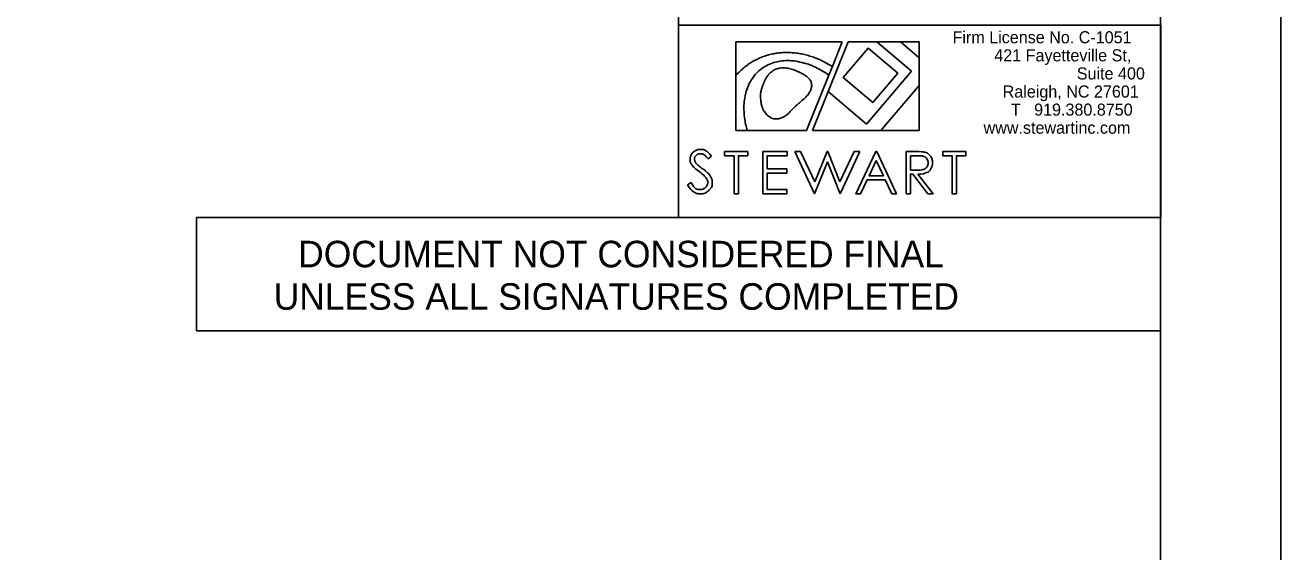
# Model space of a CAD drawing. Extents: x 972 to 1006, y 10585.8 to 10607.8.
# Drawn here: x 1000.77 to 1005.99, y 10602.35 to 10604.53 of the extents above; entities that cross this region are included whole.
import ezdxf

# ---------------------------------------------------------------- set-up
doc = ezdxf.new("R2010")
doc.units = 0
for name, color, linetype in [('Sheet Block System Information CELL', 7, 'Continuous'), ('Sheet Plan And Profile CELL', 7, 'Continuous'), ('Sheet Plan CELL', 7, 'Continuous'), ('Sheet Sticker Exception Certification CELL', 7, 'Continuous'), ('Stewart Logo', 7, 'Continuous'), ('Stewart Plot Border Xerox6279 and LJ5000', 7, 'Continuous')]:
    doc.layers.add(name, color=color, linetype=linetype)

msp = doc.modelspace()

# ---------------------------------------------------------------- linework, layer by layer
at = {"layer": 'Sheet Block System Information CELL'}
msp.add_line((1005.4881, 10604.4837), (1005.4881, 10603.737), dxfattribs=at)
at = {"layer": 'Sheet Plan And Profile CELL'}
msp.add_lwpolyline([(1003.4871, 10604.5337), (1005.4881, 10604.5337), (1005.4881, 10603.737), (1003.4871, 10603.737)], close=True, dxfattribs=at)
at = {"layer": 'Sheet Plan CELL'}
for points in [[(1005.4871, 10607.2847), (975.4871, 10607.2847), (975.4871, 10586.2847), (1005.4871, 10586.2847)], [(1003.4871, 10606.7837), (1005.4871, 10606.7837), (1005.4871, 10604.5337), (1003.4871, 10604.5337)]]:
    msp.add_lwpolyline(points, close=True, dxfattribs=at)
at = {"layer": 'Sheet Sticker Exception Certification CELL'}
for p, q in [((1001.4863, 10603.2672), (1001.4863, 10603.7372)), ((1001.4863, 10603.7372), (1005.4871, 10603.7372)), ((1005.4871, 10603.737), (1005.4871, 10603.267)), ((1005.4871, 10603.2672), (1001.4863, 10603.2672))]:
    msp.add_line(p, q, dxfattribs=at)
at = {"layer": 'Stewart Logo'}
for p, q in [((1004.1665, 10604.4649), (1003.725, 10604.4649)), ((1003.725, 10604.4649), (1003.725, 10604.3259)), ((1003.9755, 10604.4184), (1003.9757, 10604.4184)), ((1004.1911, 10604.4649), (1004.1082, 10604.2586)), ((1004.1255, 10604.3628), (1004.1665, 10604.4649)), ((1004.3102, 10604.4649), (1004.1911, 10604.4649)), ((1004.3102, 10604.4649), (1004.4532, 10604.3431)), ((1004.4081, 10604.4649), (1004.3102, 10604.4649)), ((1004.4532, 10604.3431), (1004.3102, 10604.4649)), ((1004.4858, 10604.4649), (1004.4081, 10604.4649)), ((1004.4081, 10604.4649), (1004.4858, 10604.3987)), ((1004.4858, 10604.3987), (1004.4081, 10604.4649)), ((1004.4858, 10604.3987), (1004.4858, 10604.4649)), ((1003.824, 10604.3981), (1003.8235, 10604.3975)), ((1003.8453, 10604.4062), (1003.8444, 10604.4059)), ((1003.9737, 10604.3843), (1003.9746, 10604.3847)), ((1004.0852, 10604.3852), (1004.0853, 10604.3851)), ((1004.4858, 10604.2834), (1004.4858, 10604.3987)), ((1003.725, 10604.3259), (1003.725, 10604.0969)), ((1004.0185, 10604.0969), (1004.1109, 10604.3266)), ((1004.1109, 10604.3266), (1004.1255, 10604.3628)), ((1004.4532, 10604.3431), (1004.2665, 10604.1238)), ((1004.2665, 10604.1238), (1004.4532, 10604.3431)), ((1004.2929, 10604.213), (1004.3965, 10604.3347)), ((1004.4858, 10604.2834), (1004.3269, 10604.0969)), ((1004.3269, 10604.0969), (1004.4858, 10604.2834)), ((1004.4858, 10604.0969), (1004.4858, 10604.2834)), ((1004.1082, 10604.2586), (1004.0431, 10604.0969)), ((1004.2665, 10604.1238), (1004.1082, 10604.2586)), ((1004.1082, 10604.2586), (1004.2665, 10604.1238)), ((1003.725, 10604.0969), (1003.7726, 10604.0969)), ((1003.7726, 10604.0969), (1004.0185, 10604.0969)), ((1004.0431, 10604.0969), (1004.3269, 10604.0969)), ((1004.3269, 10604.0969), (1004.4858, 10604.0969)), ((1003.9933, 10604.0103), (1003.9695, 10604.0103)), ((1003.9695, 10604.0103), (1004.0518, 10603.8353)), ((1004.0529, 10603.8842), (1003.9933, 10604.0103)), ((1004.1033, 10604.0103), (1004.0529, 10603.8842)), ((1004.1068, 10604.0103), (1004.1033, 10604.0103)), ((1004.1563, 10603.8842), (1004.1068, 10604.0103)), ((1004.2159, 10604.0103), (1004.1563, 10603.8842)), ((1004.1571, 10603.8353), (1004.2397, 10604.0103)), ((1004.2397, 10604.0103), (1004.2159, 10604.0103)), ((1004.0518, 10603.8353), (1004.105, 10603.9678)), ((1004.105, 10603.9678), (1004.1571, 10603.8353))]:
    msp.add_line(p, q, dxfattribs=at)
for points in [[(1004.1706, 10604.3171), (1004.2743, 10604.4389), (1004.3965, 10604.3347), (1004.2929, 10604.213), (1004.1706, 10604.3171)], [(1004.3965, 10604.3347), (1004.2743, 10604.4389), (1004.1706, 10604.3171), (1004.2929, 10604.213)], [(1003.8048, 10604.3887), (1003.8063, 10604.3895)], [(1004.0072, 10604.3776), (1004.0063, 10604.3772)], [(1003.7392, 10604.3404), (1003.738, 10604.3396)], [(1003.9985, 10604.2214), (1003.9961, 10604.2194)], [(1004.0022, 10604.2242), (1004.0005, 10604.223)], [(1004.0047, 10604.2258), (1004.0034, 10604.2251)], [(1003.9545, 10604.1805), (1003.9525, 10604.1785)], [(1003.6782, 10603.9931), (1003.6782, 10604.0103), (1003.774, 10604.0103), (1003.774, 10603.9931), (1003.735, 10603.9931), (1003.735, 10603.8353), (1003.7172, 10603.8353), (1003.7172, 10603.9931), (1003.6782, 10603.9931)], [(1003.8373, 10604.0103), (1003.9377, 10604.0103), (1003.9377, 10603.9931), (1003.8548, 10603.9931), (1003.8548, 10603.9383), (1003.9369, 10603.9383), (1003.9369, 10603.9212), (1003.8548, 10603.9212), (1003.8548, 10603.8524), (1003.9369, 10603.8524), (1003.9369, 10603.8353), (1003.8373, 10603.8353), (1003.8373, 10604.0103)], [(1004.3097, 10604.0103), (1004.3914, 10603.8353), (1004.3725, 10603.8353), (1004.345, 10603.893), (1004.2696, 10603.893), (1004.2424, 10603.8353), (1004.2229, 10603.8353), (1004.3055, 10604.0103), (1004.3097, 10604.0103)], [(1004.4317, 10604.0103), (1004.4664, 10604.0103)], [(1004.4806, 10603.9165), (1004.5435, 10603.8353), (1004.5218, 10603.8353), (1004.4589, 10603.9165), (1004.4491, 10603.9165), (1004.4491, 10603.8353), (1004.4317, 10603.8353), (1004.4317, 10604.0103)], [(1004.5836, 10603.9931), (1004.5836, 10604.0103), (1004.6794, 10604.0103), (1004.6794, 10603.9931), (1004.6404, 10603.9931), (1004.6404, 10603.8353), (1004.6225, 10603.8353), (1004.6225, 10603.9931), (1004.5836, 10603.9931)], [(1003.6237, 10603.9904), (1003.6095, 10603.9795)], [(1004.3075, 10603.9732), (1004.2776, 10603.9098), (1004.3374, 10603.9098), (1004.3075, 10603.9732)], [(1004.4491, 10603.9931), (1004.4491, 10603.9336), (1004.4792, 10603.9334)], [(1004.4799, 10603.9931), (1004.4491, 10603.9931)], [(1003.5244, 10603.8723), (1003.5393, 10603.8812)]]:
    msp.add_lwpolyline(points, dxfattribs=at)
for centre, radius, start, end in [((1003.9349, 10604.1386), 0.2822, 99.7438, 104.178), ((1003.9349, 10604.1386), 0.2822, 99.7438, 104.178), ((1003.9355, 10604.1349), 0.286, 95.339, 99.7438), ((1003.9355, 10604.1349), 0.286, 95.339, 99.7438), ((1003.936, 10604.1296), 0.2913, 91.0141, 95.339), ((1003.936, 10604.1296), 0.2913, 91.0141, 95.339), ((1003.9363, 10604.1119), 0.309, 86.8145, 91.0141), ((1003.9363, 10604.1119), 0.309, 86.8145, 91.0141), ((1003.9363, 10604.1119), 0.309, 82.6822, 86.8145), ((1003.9363, 10604.1119), 0.309, 82.6822, 86.8145), ((1003.9324, 10604.0825), 0.3386, 78.75, 82.6822), ((1003.9324, 10604.0825), 0.3386, 78.75, 82.6822), ((1003.9477, 10604.1276), 0.2979, 126.3831, 130.5125), ((1003.9477, 10604.1276), 0.2979, 126.3831, 130.5125), ((1003.9265, 10604.1564), 0.2622, 121.981, 126.3831), ((1003.9265, 10604.1564), 0.2622, 121.981, 126.3831), ((1003.9388, 10604.1367), 0.2855, 117.649, 121.981), ((1003.9388, 10604.1367), 0.2855, 117.649, 121.981), ((1003.9265, 10604.1564), 0.2622, 113.1331, 117.649), ((1003.9265, 10604.1564), 0.2622, 113.1331, 117.649), ((1003.9349, 10604.1386), 0.2822, 108.6948, 113.1331), ((1003.9349, 10604.1386), 0.2822, 108.6948, 113.1331), ((1003.9273, 10604.224), 0.1613, 114.2575, 124.1721), ((1003.9273, 10604.224), 0.1613, 114.2575, 124.1721), ((1003.932, 10604.1499), 0.2705, 104.178, 108.6948), ((1003.932, 10604.1499), 0.2705, 104.178, 108.6948), ((1003.9369, 10604.2029), 0.1845, 104.9898, 114.2575), ((1003.9369, 10604.2029), 0.1845, 104.9898, 114.2575), ((1003.9339, 10604.2139), 0.1731, 95.9703, 104.9898), ((1003.9339, 10604.2139), 0.1731, 95.9703, 104.9898), ((1003.9408, 10604.1482), 0.2391, 88.2991, 95.9703), ((1003.9408, 10604.1482), 0.2391, 88.2991, 95.9703), ((1003.9418, 10604.1832), 0.2041, 80.7637, 88.2991), ((1003.9418, 10604.1832), 0.2041, 80.7637, 88.2991), ((1003.9231, 10604.0726), 0.3158, 74.7103, 80.7637), ((1003.9231, 10604.0726), 0.3158, 74.7103, 80.7637), ((1003.9347, 10604.094), 0.3269, 74.8634, 78.75), ((1003.9347, 10604.094), 0.3269, 74.8634, 78.75), ((1003.9429, 10604.1424), 0.2439, 68.5824, 74.7103), ((1003.9429, 10604.1424), 0.2439, 68.5824, 74.7103), ((1003.9225, 10604.0489), 0.3736, 71.2279, 74.8634), ((1003.9225, 10604.0489), 0.3736, 71.2279, 74.8634), ((1003.8859, 10603.9971), 0.3999, 63.7978, 68.5824), ((1003.8859, 10603.9971), 0.3999, 63.7978, 68.5824), ((1003.9299, 10604.0708), 0.3505, 67.6108, 71.2279), ((1003.9299, 10604.0708), 0.3505, 67.6108, 71.2279), ((1003.9065, 10604.014), 0.4119, 64.2747, 67.6108), ((1003.9065, 10604.014), 0.4119, 64.2747, 67.6108), ((1003.9136, 10604.029), 0.3953, 60.9284, 64.2747), ((1003.9136, 10604.029), 0.3953, 60.9284, 64.2747), ((1003.9136, 10604.029), 0.3953, 57.5922, 60.9284), ((1003.9136, 10604.029), 0.3953, 57.5922, 60.9284), ((1003.9388, 10604.1367), 0.2855, 134.7069, 138.485), ((1003.9388, 10604.1367), 0.2855, 134.7069, 138.485), ((1003.9345, 10604.1431), 0.2776, 130.5125, 134.7069), ((1003.9345, 10604.1431), 0.2776, 130.5125, 134.7069), ((1003.9274, 10604.2212), 0.1631, 143.7045, 153.1024), ((1003.9274, 10604.2212), 0.1631, 143.7045, 153.1024), ((1003.9381, 10604.2134), 0.1764, 134.1821, 143.7045), ((1003.9381, 10604.2134), 0.1764, 134.1821, 143.7045), ((1003.9264, 10604.2254), 0.1597, 124.1721, 134.1821), ((1003.9264, 10604.2254), 0.1597, 124.1721, 134.1821), ((1003.9759, 10604.2393), 0.1466, 150.0914, 154.7022), ((1003.9759, 10604.2393), 0.1466, 150.0914, 154.7022), ((1003.9489, 10604.2548), 0.1154, 144.895, 150.0914), ((1003.9489, 10604.2548), 0.1154, 144.895, 150.0914), ((1003.9407, 10604.2606), 0.1054, 139.1543, 144.895), ((1003.9407, 10604.2606), 0.1054, 139.1543, 144.895), ((1003.927, 10604.2724), 0.0874, 132.8496, 139.1543), ((1003.927, 10604.2724), 0.0874, 132.8496, 139.1543), ((1003.9233, 10604.2764), 0.0819, 126.1002, 132.8496), ((1003.9233, 10604.2764), 0.0819, 126.1002, 132.8496), ((1003.919, 10604.2823), 0.0746, 119.026, 126.1002), ((1003.919, 10604.2823), 0.0746, 119.026, 126.1002), ((1003.9184, 10604.2835), 0.0733, 111.8278, 119.026), ((1003.9184, 10604.2835), 0.0733, 111.8278, 119.026), ((1003.9191, 10604.2816), 0.0753, 104.7285, 111.8278), ((1003.9191, 10604.2816), 0.0753, 104.7285, 111.8278), ((1003.9198, 10604.279), 0.078, 97.9017, 104.7285), ((1003.9198, 10604.279), 0.078, 97.9017, 104.7285), ((1003.9214, 10604.2673), 0.0898, 91.5398, 97.9017), ((1003.9214, 10604.2673), 0.0898, 91.5398, 97.9017), ((1003.9216, 10604.2604), 0.0968, 85.6825, 91.5398), ((1003.9216, 10604.2604), 0.0968, 85.6825, 91.5398), ((1003.9199, 10604.237), 0.1202, 80.427, 85.6825), ((1003.9199, 10604.237), 0.1202, 80.427, 85.6825), ((1003.9179, 10604.2256), 0.1317, 75.6971, 80.427), ((1003.9179, 10604.2256), 0.1317, 75.6971, 80.427), ((1003.9086, 10604.1889), 0.1697, 71.5292, 75.6971), ((1003.9086, 10604.1889), 0.1697, 71.5292, 75.6971), ((1003.8957, 10604.1503), 0.2103, 67.7999, 71.5292), ((1003.8957, 10604.1503), 0.2103, 67.7999, 71.5292), ((1003.9115, 10604.1891), 0.1684, 63.632, 67.7999), ((1003.9115, 10604.1891), 0.1684, 63.632, 67.7999), ((1003.9364, 10604.2178), 0.132, 63.9022, 67.7899), ((1003.9364, 10604.2178), 0.132, 63.9022, 67.7899), ((1003.9183, 10604.1807), 0.1733, 60.5091, 63.9022), ((1003.9183, 10604.1807), 0.1733, 60.5091, 63.9022), ((1003.938, 10604.2155), 0.1333, 56.6214, 60.5091), ((1003.938, 10604.2155), 0.1333, 56.6214, 60.5091), ((1003.9576, 10604.2454), 0.0975, 52.0757, 56.6214), ((1003.9576, 10604.2454), 0.0975, 52.0757, 56.6214), ((1003.9648, 10604.2546), 0.0858, 46.8444, 52.0757), ((1003.9648, 10604.2546), 0.0858, 46.8444, 52.0757), ((1003.9799, 10604.2707), 0.0638, 40.7768, 46.8444), ((1003.9799, 10604.2707), 0.0638, 40.7768, 46.8444), ((1003.9853, 10604.2753), 0.0567, 33.8961, 40.7768), ((1003.9853, 10604.2753), 0.0567, 33.8961, 40.7768), ((1003.9231, 10604.0726), 0.3158, 58.7784, 63.7978), ((1003.9231, 10604.0726), 0.3158, 58.7784, 63.7978), ((1003.9066, 10604.0454), 0.3475, 53.9938, 58.7784), ((1003.9066, 10604.0454), 0.3475, 53.9938, 58.7784), ((1003.9478, 10604.2056), 0.1881, 161.1689, 169.1279), ((1003.9478, 10604.2056), 0.1881, 161.1689, 169.1279), ((1003.9793, 10604.1949), 0.2213, 153.1024, 161.1689), ((1003.9793, 10604.1949), 0.2213, 153.1024, 161.1689), ((1004.0314, 10604.2134), 0.2075, 165.6937, 169.3181), ((1004.0314, 10604.2134), 0.2075, 165.6937, 169.3181), ((1004.0814, 10604.2006), 0.2591, 162.4501, 165.6937), ((1004.0814, 10604.2006), 0.2591, 162.4501, 165.6937), ((1004.034, 10604.2156), 0.2093, 158.8258, 162.4501), ((1004.034, 10604.2156), 0.2093, 158.8258, 162.4501), ((1003.9896, 10604.2328), 0.1617, 154.7022, 158.8258), ((1003.9896, 10604.2328), 0.1617, 154.7022, 158.8258), ((1003.955, 10604.3013), 0.0882, 326.7539, 331.8907), ((1003.955, 10604.3013), 0.0882, 326.7539, 331.8907), ((1003.9948, 10604.2817), 0.0452, 26.1882, 33.8961), ((1003.9948, 10604.2817), 0.0452, 26.1882, 33.8961), ((1003.975, 10604.2906), 0.0655, 331.8907, 337.8545), ((1003.975, 10604.2906), 0.0655, 331.8907, 337.8545), ((1003.9977, 10604.2831), 0.042, 17.8594, 26.1882), ((1003.9977, 10604.2831), 0.042, 17.8594, 26.1882), ((1003.9819, 10604.2878), 0.0581, 337.8545, 344.6304), ((1003.9819, 10604.2878), 0.0581, 337.8545, 344.6304), ((1004.0009, 10604.2842), 0.0386, 9.1711, 17.8594), ((1004.0009, 10604.2842), 0.0386, 9.1711, 17.8594), ((1003.9935, 10604.2846), 0.046, 344.6304, 352.2444), ((1003.9935, 10604.2846), 0.046, 344.6304, 352.2444), ((1004.0008, 10604.2842), 0.0387, 0.507, 9.1711), ((1004.0008, 10604.2842), 0.0387, 0.507, 9.1711), ((1003.997, 10604.2841), 0.0425, 352.2444, 0.507), ((1003.997, 10604.2841), 0.0425, 352.2444, 0.507), ((1003.983, 10604.1914), 0.225, 175.5255, 181.9873), ((1003.983, 10604.1914), 0.225, 175.5255, 181.9873), ((1004.0488, 10604.1862), 0.291, 169.1279, 175.5255), ((1004.0488, 10604.1862), 0.291, 169.1279, 175.5255), ((1003.9787, 10604.2385), 0.1518, 174.9583, 179.1125), ((1003.9787, 10604.2385), 0.1518, 174.9583, 179.1125), ((1003.9625, 10604.2388), 0.1356, 179.1125, 183.5072), ((1003.9625, 10604.2388), 0.1356, 179.1125, 183.5072), ((1004.0019, 10604.2412), 0.175, 183.5072, 187.6613), ((1004.0019, 10604.2412), 0.175, 183.5072, 187.6613), ((1003.9352, 10604.2322), 0.1078, 187.6614, 192.9555), ((1003.9352, 10604.2322), 0.1078, 187.6614, 192.9555), ((1003.9665, 10604.2394), 0.1398, 192.9555, 198.184), ((1003.9665, 10604.2394), 0.1398, 192.9555, 198.184), ((1004.4722, 10603.6717), 0.7257, 132.3943, 132.7975), ((1004.4722, 10603.6717), 0.7257, 132.3943, 132.7975), ((1004.4285, 10603.7196), 0.6609, 131.9515, 132.3943), ((1004.4285, 10603.7196), 0.6609, 131.9515, 132.3943), ((1004.3498, 10603.807), 0.5433, 131.4632, 131.9515), ((1004.3498, 10603.807), 0.5433, 131.4632, 131.9515), ((1004.2577, 10603.9113), 0.4042, 130.8651, 131.4632), ((1004.2577, 10603.9113), 0.4042, 130.8651, 131.4632), ((1004.2001, 10603.9779), 0.3161, 130.1887, 130.8651), ((1004.2001, 10603.9779), 0.3161, 130.1887, 130.8651), ((1004.119, 10604.0739), 0.1905, 129.2494, 130.1887), ((1004.0822, 10604.119), 0.1322, 128.1219, 129.2494), ((1004.0822, 10604.119), 0.1322, 128.1219, 129.2494), ((1004.0394, 10604.1735), 0.0629, 126.2742, 128.1219), ((1004.0216, 10604.1978), 0.0329, 123.718, 126.2741), ((1004.0216, 10604.1978), 0.0329, 123.718, 126.2741), ((1004.0061, 10604.2209), 0.00499, 118.0607, 123.718), ((1004.0153, 10604.2038), 0.0244, 115.5046, 118.0608), ((1003.9152, 10604.3277), 0.1356, 311.3243, 315.1414), ((1003.9152, 10604.3277), 0.1356, 311.3243, 315.1414), ((1003.8852, 10604.3575), 0.1779, 315.1414, 318.4744), ((1003.8852, 10604.3575), 0.1779, 315.1414, 318.4744), ((1003.9159, 10604.3304), 0.137, 318.4744, 322.2915), ((1003.9159, 10604.3304), 0.137, 318.4744, 322.2915), ((1003.9449, 10604.3079), 0.1002, 322.2915, 326.7539), ((1003.9449, 10604.3079), 0.1002, 322.2915, 326.7539), ((1004.1299, 10604.1965), 0.3719, 181.9873, 187.0116), ((1004.1299, 10604.1965), 0.3719, 181.9873, 187.0116), ((1003.9182, 10604.2236), 0.0891, 198.184, 204.7361), ((1003.9182, 10604.2236), 0.0891, 198.184, 204.7361), ((1003.9307, 10604.2293), 0.1028, 204.7361, 211.5103), ((1003.9307, 10604.2293), 0.1028, 204.7361, 211.5103), ((1003.9032, 10604.2125), 0.0706, 211.5103, 219.6861), ((1003.9032, 10604.2125), 0.0706, 211.5103, 219.6861), ((1003.9047, 10604.2136), 0.0724, 219.6861, 228.4088), ((1003.9047, 10604.2136), 0.0724, 219.6861, 228.4088), ((1003.8949, 10604.2026), 0.0577, 228.4088, 238.184), ((1003.8949, 10604.2026), 0.0577, 228.4088, 238.184), ((1003.8921, 10604.2114), 0.0655, 295.379, 302.7203), ((1003.8921, 10604.2114), 0.0655, 295.379, 302.7203), ((1003.8668, 10604.2508), 0.1123, 302.7203, 308.3257), ((1003.8668, 10604.2508), 0.1123, 302.7203, 308.3257), ((1003.8783, 10604.2362), 0.0937, 308.3257, 314.0568), ((1003.8783, 10604.2362), 0.0937, 308.3257, 314.0568), ((1003.8754, 10604.2392), 0.0979, 314.0568, 319.6622), ((1003.8754, 10604.2392), 0.0979, 314.0568, 319.6622), ((1004.3511, 10603.7914), 0.5556, 135.8419, 136.2162), ((1004.3511, 10603.7914), 0.5556, 135.8419, 136.2162), ((1004.2031, 10603.9351), 0.3493, 135.3698, 135.8419), ((1004.4189, 10603.7221), 0.6526, 134.9955, 135.3698), ((1004.4189, 10603.7221), 0.6526, 134.9955, 135.3698), ((1004.3525, 10603.7886), 0.5586, 134.5909, 134.9955), ((1004.3525, 10603.7886), 0.5586, 134.5909, 134.9955), ((1004.5549, 10603.5832), 0.847, 134.2487, 134.5909), ((1004.5549, 10603.5832), 0.847, 134.2487, 134.5909), ((1004.4629, 10603.6776), 0.7151, 133.8764, 134.2487), ((1004.4629, 10603.6776), 0.7151, 133.8764, 134.2487), ((1004.6166, 10603.5178), 0.9368, 133.5368, 133.8764), ((1004.6166, 10603.5178), 0.9368, 133.5368, 133.8764), ((1004.5134, 10603.6264), 0.787, 133.1663, 133.5368), ((1004.5134, 10603.6264), 0.787, 133.1663, 133.5368), ((1004.5687, 10603.5674), 0.8679, 132.7975, 133.1663), ((1004.5687, 10603.5674), 0.8679, 132.7975, 133.1663), ((1004.0557, 10604.1873), 0.2971, 187.0116, 192.2545), ((1004.0557, 10604.1873), 0.2971, 187.0116, 192.2545), ((1004.0815, 10604.1929), 0.3235, 192.2545, 197.2789), ((1004.0815, 10604.1929), 0.3235, 192.2545, 197.2789), ((1003.893, 10604.1997), 0.0542, 238.184, 248.5685), ((1003.893, 10604.1997), 0.0542, 238.184, 248.5685), ((1003.8932, 10604.2), 0.0546, 248.5685, 258.9188), ((1003.8932, 10604.2), 0.0546, 248.5685, 258.9188), ((1003.892, 10604.1942), 0.0486, 258.9188, 269.5093), ((1003.892, 10604.1942), 0.0486, 258.9188, 269.5093), ((1003.8921, 10604.2088), 0.0632, 269.5093, 278.793), ((1003.8921, 10604.2088), 0.0632, 269.5093, 278.793), ((1003.8936, 10604.1991), 0.0534, 278.793, 288.0103), ((1003.8936, 10604.1991), 0.0534, 278.793, 288.0103), ((1003.8843, 10604.2277), 0.0835, 288.0103, 295.379), ((1003.8843, 10604.2277), 0.0835, 288.0103, 295.379)]:
    msp.add_arc(centre, radius, start, end, dxfattribs=at)
for points in [[(1003.6095, 10603.9795), (1003.5996, 10603.9926), (1003.5926, 10603.9968), (1003.5857, 10604.0009), (1003.5775, 10604.0009), (1003.5669, 10604.0009), (1003.5602, 10603.9945), (1003.5534, 10603.9881), (1003.5534, 10603.9787), (1003.5534, 10603.973), (1003.5558, 10603.9676), (1003.5582, 10603.9623), (1003.5645, 10603.956), (1003.5679, 10603.9526), (1003.5871, 10603.9385), (1003.6098, 10603.9217), (1003.6183, 10603.9086), (1003.6267, 10603.8956), (1003.6267, 10603.8824), (1003.6267, 10603.8633), (1003.6123, 10603.8493), (1003.5978, 10603.8353), (1003.5772, 10603.8353), (1003.5612, 10603.8353), (1003.5483, 10603.8438), (1003.5353, 10603.8523), (1003.5244, 10603.8723)], [(1003.5393, 10603.8812), (1003.555, 10603.8523), (1003.5755, 10603.8523), (1003.5843, 10603.8523), (1003.592, 10603.8564), (1003.5998, 10603.8605), (1003.6038, 10603.8674), (1003.6079, 10603.8743), (1003.6079, 10603.882), (1003.6079, 10603.8908), (1003.6019, 10603.8992), (1003.5937, 10603.9109), (1003.5719, 10603.9273), (1003.5501, 10603.9439), (1003.5447, 10603.9512), (1003.5354, 10603.9636), (1003.5354, 10603.978), (1003.5354, 10603.9894), (1003.5409, 10603.9988), (1003.5464, 10604.0082), (1003.5563, 10604.0136), (1003.5662, 10604.0191), (1003.5779, 10604.0191), (1003.5902, 10604.0191), (1003.601, 10604.0129), (1003.6117, 10604.0068), (1003.6237, 10603.9904)], [(1004.4664, 10604.0103), (1004.4955, 10604.0103), (1004.5059, 10604.0079), (1004.5214, 10604.0043), (1004.5312, 10603.9926), (1004.5409, 10603.9808), (1004.5409, 10603.9637), (1004.5409, 10603.9494), (1004.5342, 10603.9385), (1004.5275, 10603.9277), (1004.515, 10603.9221), (1004.5025, 10603.9166), (1004.4806, 10603.9165)], [(1004.4792, 10603.9334), (1004.4967, 10603.9334), (1004.5051, 10603.9367), (1004.5135, 10603.94), (1004.5182, 10603.9474), (1004.5229, 10603.9547), (1004.5229, 10603.9637), (1004.5229, 10603.9725), (1004.5181, 10603.9797), (1004.5134, 10603.9869), (1004.5056, 10603.99), (1004.4979, 10603.9931), (1004.4799, 10603.9931)]]:
    msp.add_open_spline(points, degree=3, dxfattribs=at)
at = {"layer": 'Stewart Plot Border Xerox6279 and LJ5000'}
msp.add_lwpolyline([(971.9871, 10585.7847), (1005.9871, 10585.7847), (1005.9871, 10607.7847), (971.9871, 10607.7847)], close=True, dxfattribs=at)

# ---------------------------------------------------------------- texts
at = {"layer": 'Sheet Sticker Exception Certification CELL'}
for s, p in [('DOCUMENT NOT CONSIDERED FINAL', (1001.9078, 10603.5303)), ('UNLESS ALL SIGNATURES COMPLETED', (1001.8063, 10603.3543))]:
    msp.add_text(s, height=0.11, dxfattribs=at).set_placement(p)
at = {"layer": 'Stewart Logo'}
for s, p in [('Firm License No. C-1051', (1004.6241, 10604.459)), ('421 Fayetteville St,', (1004.7975, 10604.384)), ('Suite 400', (1005.14, 10604.309)), ('Raleigh, NC 27601', (1004.8322, 10604.234)), ('T   919.380.8750', (1004.8662, 10604.159)), ('www.stewartinc.com', (1004.753, 10604.084))]:
    msp.add_text(s, height=0.05, rotation=0, dxfattribs=at).set_placement(p)

doc.saveas('drawing.dxf')
